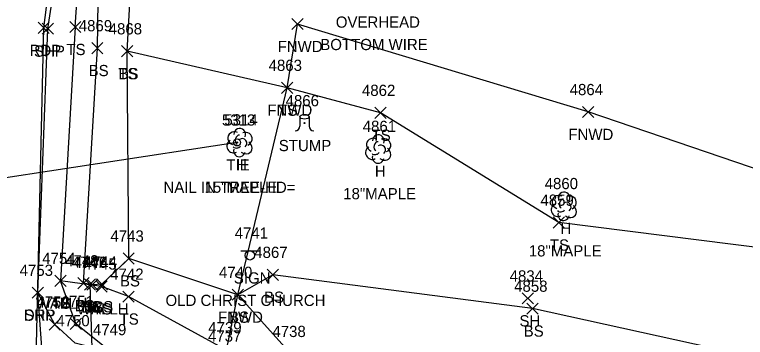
# Model space of a CAD drawing. Extents: x 1601151 to 1602912, y 499508 to 501770.
# Drawn here: x 1601465.7 to 1601596, y 501249.2 to 501306.7 of the extents above; entities that cross this region are included whole.
import ezdxf

# ---------------------------------------------------------------- set-up
doc = ezdxf.new("R2010")
doc.units = 0
for name, color, linetype in [('C_A', 7, 'Continuous'), ('C_C', 7, 'Continuous'), ('C_I', 7, 'Continuous'), ('CBP', 7, 'Continuous'), ('CBT', 7, 'Continuous'), ('D_A', 7, 'Continuous'), ('D_I', 7, 'Continuous'), ('D_TIC', 7, 'Continuous'), ('DCP', 7, 'Continuous'), ('DHW', 7, 'Continuous'), ('L_A', 7, 'Continuous'), ('L_C', 7, 'Continuous'), ('L_I', 7, 'Continuous'), ('L_TIC', 7, 'Continuous'), ('LELB', 7, 'Continuous'), ('LFNC', 7, 'Continuous'), ('LTD', 7, 'Continuous'), ('LTS', 7, 'Continuous'), ('P_A', 7, 'Continuous'), ('P_I', 7, 'Continuous'), ('P_TIC', 7, 'Continuous'), ('PET', 7, 'Continuous'), ('PSP', 7, 'Continuous'), ('R_A', 7, 'Continuous'), ('R_I', 7, 'Continuous'), ('R_TIC', 7, 'Continuous'), ('RDP', 7, 'Continuous'), ('S_A', 7, 'Continuous'), ('S_C', 7, 'Continuous'), ('S_I', 7, 'Continuous'), ('SSGN', 7, 'Continuous'), ('U_A', 7, 'Continuous'), ('U_C', 7, 'Continuous')]:
    doc.layers.add(name, color=color, linetype=linetype)

msp = doc.modelspace()

# ---------------------------------------------------------------- linework, layer by layer
at = {"layer": 'CBP'}
for radius in [0.625, 0.0833]:
    msp.add_circle((1601505.35, 501283.95), radius, dxfattribs=at)
at = {"layer": 'CBT'}
msp.add_lwpolyline([(1601505.35, 501283.95), (1601430.56, 501272.53)], dxfattribs=at)
at = {"layer": 'D_TIC'}
for points in [[(1601472.85, 501258.29), (1601474.85, 501260.29)], [(1601474.85, 501258.29), (1601472.85, 501260.29)], [(1601478.12, 501257.61), (1601480.12, 501259.61)], [(1601480.12, 501257.61), (1601478.12, 501259.61)], [(1601480.19, 501257.28), (1601482.19, 501259.28)], [(1601482.19, 501257.28), (1601480.19, 501259.28)]]:
    msp.add_lwpolyline(points, dxfattribs=at)
at = {"layer": 'DCP'}
msp.add_lwpolyline([(1601480.01, 501230.14), (1601479.12, 501258.61)], dxfattribs=at)
at = {"layer": 'DHW'}
msp.add_lwpolyline([(1601481.19, 501258.28), (1601473.85, 501259.29)], dxfattribs=at)
at = {"layer": 'L_TIC'}
for points in [[(1601475.49, 501303.53), (1601477.49, 501305.53)], [(1601477.49, 501303.53), (1601475.49, 501305.53)], [(1601515.13, 501304.06), (1601517.13, 501306.06)], [(1601517.13, 501304.06), (1601515.13, 501306.06)], [(1601515.13, 501304.06), (1601517.13, 501306.06)], [(1601517.13, 501304.06), (1601515.13, 501306.06)], [(1601479.43, 501299.77), (1601481.43, 501301.77)], [(1601481.43, 501299.77), (1601479.43, 501301.77)], [(1601484.76, 501299.21), (1601486.76, 501301.21)], [(1601486.76, 501299.21), (1601484.76, 501301.21)], [(1601484.76, 501299.21), (1601486.76, 501301.21)], [(1601486.76, 501299.21), (1601484.76, 501301.21)], [(1601513.29, 501292.7), (1601515.29, 501294.7)], [(1601515.29, 501292.7), (1601513.29, 501294.7)], [(1601513.29, 501292.7), (1601515.29, 501294.7)], [(1601515.29, 501292.7), (1601513.29, 501294.7)], [(1601529.94, 501288.24), (1601531.94, 501290.24)], [(1601531.94, 501288.24), (1601529.94, 501290.24)], [(1601567, 501288.38), (1601569, 501290.38)], [(1601569, 501288.38), (1601567, 501290.38)], [(1601561.75, 501268.66), (1601563.75, 501270.66)], [(1601563.75, 501268.66), (1601561.75, 501270.66)], [(1601485.02, 501262.27), (1601487.02, 501264.27)], [(1601487.02, 501262.27), (1601485.02, 501264.27)], [(1601485.02, 501262.27), (1601487.02, 501264.27)], [(1601487.02, 501262.27), (1601485.02, 501264.27)], [(1601510.72, 501259.36), (1601512.72, 501261.36)], [(1601512.72, 501259.36), (1601510.72, 501261.36)], [(1601472.85, 501258.29), (1601474.85, 501260.29)], [(1601474.85, 501258.29), (1601472.85, 501260.29)], [(1601476.94, 501257.85), (1601478.94, 501259.85)], [(1601478.94, 501257.85), (1601476.94, 501259.85)], [(1601478.12, 501257.61), (1601480.12, 501259.61)], [(1601480.12, 501257.61), (1601478.12, 501259.61)], [(1601478.54, 501257.59), (1601480.54, 501259.59)], [(1601480.54, 501257.59), (1601478.54, 501259.59)], [(1601480.25, 501257.66), (1601482.25, 501259.66)], [(1601482.25, 501257.66), (1601480.25, 501259.66)], [(1601480.19, 501257.28), (1601482.19, 501259.28)], [(1601482.19, 501257.28), (1601480.19, 501259.28)], [(1601484.98, 501255.46), (1601486.98, 501257.46)], [(1601486.98, 501255.46), (1601484.98, 501257.46)], [(1601504.47, 501255.8), (1601506.47, 501257.8)], [(1601506.47, 501255.8), (1601504.47, 501257.8)], [(1601504.47, 501255.8), (1601506.47, 501257.8)], [(1601506.47, 501255.8), (1601504.47, 501257.8)], [(1601556.24, 501255.15), (1601558.24, 501257.15)], [(1601558.24, 501255.15), (1601556.24, 501257.15)], [(1601557.05, 501253.32), (1601559.05, 501255.32)], [(1601559.05, 501253.32), (1601557.05, 501255.32)], [(1601475.57, 501250.6), (1601477.57, 501252.6)], [(1601477.57, 501250.6), (1601475.57, 501252.6)]]:
    msp.add_lwpolyline(points, dxfattribs=at)
at = {"layer": 'LELB'}
for points in [[(1601476.49, 501304.53), (1601478.93, 501340.78), (1601483.82, 501372.17), (1601493.27, 501419.11), (1601502.01, 501462.34), (1601513.24, 501514.09), (1601519.29, 501544.8)], [(1601486.02, 501263.27), (1601481.25, 501258.66), (1601479.54, 501258.59), (1601479.12, 501258.61), (1601477.94, 501258.85), (1601480.43, 501300.77), (1601480.94, 501334.18), (1601485.69, 501371.5), (1601485.76, 501372.59), (1601494.84, 501418.67), (1601503.71, 501461.98), (1601514.66, 501513.83), (1601522.81, 501541.12), (1601521.69, 501544.36)], [(1601514.92, 501246.25), (1601505.47, 501256.8), (1601486.02, 501263.27), (1601485.76, 501300.21), (1601487.94, 501339.81), (1601496.98, 501373.17)], [(1601476.49, 501304.53), (1601473.85, 501259.29)], [(1601666.94, 501224.13), (1601649.13, 501230.84), (1601644.06, 501241.55), (1601653.65, 501247.39), (1601634.42, 501254.81), (1601606.58, 501264.14), (1601562.75, 501269.66), (1601530.94, 501289.24), (1601514.29, 501293.7), (1601485.76, 501300.21)], [(1601511.72, 501260.36), (1601505.47, 501256.8)], [(1601664.07, 501218.13), (1601645.33, 501229.07), (1601628.63, 501238.53), (1601602.89, 501244.46), (1601558.05, 501254.32), (1601511.72, 501260.36)], [(1601482.9, 501246.57), (1601476.57, 501251.6), (1601473.85, 501259.29)], [(1601514.92, 501246.25), (1601503.48, 501246.93), (1601485.98, 501256.46), (1601481.19, 501258.28)]]:
    msp.add_lwpolyline(points, dxfattribs=at)
at = {"layer": 'LFNC'}
for points in [[(1601503.43, 501245.43), (1601503.48, 501246.93), (1601505.47, 501256.8), (1601514.29, 501293.7), (1601516.13, 501305.06)], [(1601673.34, 501255.62), (1601634.03, 501267.87), (1601610.24, 501275.02), (1601568, 501289.38), (1601516.13, 501305.06)]]:
    msp.add_lwpolyline(points, dxfattribs=at)
at = {"layer": 'LTD'}
for p, q in [((1601505.77, 501283.98), (1601505.77, 501283.98)), ((1601505.77, 501283.98), (1601505.77, 501283.98)), ((1601530.51, 501282.82), (1601530.51, 501282.82)), ((1601530.51, 501282.82), (1601530.51, 501282.82)), ((1601563.62, 501272.62), (1601563.62, 501272.62)), ((1601563.62, 501272.62), (1601563.62, 501272.62))]:
    msp.add_line(p, q, dxfattribs=at)
for centre in [(1601505.82, 501285.41), (1601530.56, 501284.25), (1601563.67, 501274.05)]:
    msp.add_arc(centre, 1.05, 335.5272, 180.9563, dxfattribs=at)
for centre, major_axis, ratio, start_param, end_param in [((1601504.98, 501284.64), (1.21, -0.51), 0.895232, 1.570796, 4.712389), ((1601506.81, 501284.56), (-1.14, -0.48), 0.949671, 1.570796, 4.712389), ((1601504.69, 501283.27), (0.58, -1.04), 0.959034, 3.141593, 6.283185), ((1601505.56, 501284.44), (-0.208, -0.792), 0.645439, 3.141593, 6.283185), ((1601506.27, 501283.81), (-0.5, 0.667), 0.989748, 3.141593, 6.283185), ((1601529.72, 501283.49), (1.21, -0.51), 0.895232, 1.570796, 4.712389), ((1601530.3, 501283.28), (-0.208, -0.792), 0.645439, 3.141593, 6.283185), ((1601531.55, 501283.4), (-1.14, -0.48), 0.949671, 1.570796, 4.712389), ((1601505.31, 501283.23), (-0.625, -0.083), 0.423636, 0, 3.141593), ((1601506.77, 501283.15), (-1.09, 0.79), 0.841452, 1.570796, 4.712389), ((1601529.43, 501282.11), (0.58, -1.04), 0.959034, 3.141593, 6.283185), ((1601531.01, 501282.65), (-0.5, 0.667), 0.989748, 3.141593, 6.283185), ((1601531.51, 501281.99), (-1.09, 0.79), 0.841452, 1.570796, 4.712389), ((1601505.77, 501282.48), (0.26, 1.06), 0.942809, 1.570796, 4.712389), ((1601530.51, 501281.32), (0.26, 1.06), 0.942809, 1.570796, 4.712389), ((1601530.05, 501282.07), (-0.625, -0.083), 0.423636, 0, 3.141593), ((1601562.83, 501273.28), (1.21, -0.51), 0.895232, 1.570796, 4.712389), ((1601563.41, 501273.07), (-0.208, -0.792), 0.645439, 3.141593, 6.283185), ((1601564.66, 501273.2), (-1.14, -0.48), 0.949671, 1.570796, 4.712389), ((1601562.54, 501271.91), (0.58, -1.04), 0.959034, 3.141593, 6.283185), ((1601564.12, 501272.45), (-0.5, 0.667), 0.989748, 3.141593, 6.283185), ((1601564.62, 501271.78), (-1.09, 0.79), 0.841452, 1.570796, 4.712389), ((1601563.62, 501271.12), (0.26, 1.06), 0.942809, 1.570796, 4.712389), ((1601563.16, 501271.87), (-0.625, -0.083), 0.423636, 0, 3.141593)]:
    msp.add_ellipse(centre, major_axis=major_axis, ratio=ratio, start_param=start_param, end_param=end_param, dxfattribs=at)
at = {"layer": 'LTS'}
for p, q in [((1601516.54, 501288.54), (1601516.54, 501286.87)), ((1601518.21, 501288.37), (1601518.21, 501288.54)), ((1601518.21, 501288.54), (1601518.21, 501286.87)), ((1601517.38, 501287.4), (1601517.38, 501287.4)), ((1601517.38, 501287.4), (1601517.38, 501287.4)), ((1601517.38, 501287.37), (1601517.38, 501287.37))]:
    msp.add_line(p, q, dxfattribs=at)
msp.add_circle((1601517.38, 501287.4), 0.0833, dxfattribs=at)
for centre, start, end in [((1601515.71, 501286.87), 270, 360), ((1601519.04, 501286.87), 180, 270)]:
    msp.add_arc(centre, 0.833, start, end, dxfattribs=at)
msp.add_ellipse((1601517.38, 501288.54), major_axis=(-0.833, 0), ratio=0.5, dxfattribs=at)
at = {"layer": 'P_TIC'}
for points in [[(1601469.85, 501303.37), (1601471.85, 501305.37)], [(1601471.85, 501303.37), (1601469.85, 501305.37)], [(1601470.6, 501303.23), (1601472.6, 501305.23)], [(1601472.6, 501303.23), (1601470.6, 501305.23)], [(1601468.82, 501256.16), (1601470.82, 501258.16)], [(1601470.82, 501256.16), (1601468.82, 501258.16)]]:
    msp.add_lwpolyline(points, dxfattribs=at)
at = {"layer": 'PET'}
msp.add_lwpolyline([(1601544.22, 500876.26), (1601539.18, 500895.59), (1601526.95, 500943.37), (1601516.32, 500985.83), (1601505.44, 501027.92), (1601495.1, 501070.93), (1601487, 501107.14), (1601479.48, 501143.91), (1601474.16, 501178.21), (1601471.72, 501199.66), (1601469.2, 501232.53), (1601470.85, 501304.37), (1601475.76, 501342.26), (1601481.23, 501372.74), (1601489.71, 501419.6), (1601498.83, 501463.24), (1601509.83, 501514.72), (1601518.29, 501552.56), (1601529.19, 501602.72), (1601530.09, 501606.93), (1601533.57, 501622.36), (1601544.66, 501669.88)], dxfattribs=at)
at = {"layer": 'PSP'}
msp.add_lwpolyline([(1601528.9, 500943.6), (1601517.98, 500986.13), (1601507.44, 501028.32), (1601496.62, 501071.21), (1601488.24, 501107.28), (1601480.68, 501144.12), (1601475.12, 501178.17), (1601472.51, 501199.52), (1601470.88, 501228.6), (1601471.76, 501230.34), (1601469.82, 501257.16), (1601471.6, 501304.23), (1601477.35, 501341.75), (1601482.3, 501372.17), (1601491.34, 501419.44), (1601500.56, 501462.85), (1601511.15, 501514.36), (1601520.07, 501552.2), (1601531.25, 501603.07), (1601534.57, 501619.48), (1601535.23, 501620.04), (1601536.15, 501623.42), (1601535.02, 501624.1), (1601546.22, 501669.66)], dxfattribs=at)
at = {"layer": 'R_TIC'}
for points in [[(1601468.82, 501256.16), (1601470.82, 501258.16)], [(1601470.82, 501256.16), (1601468.82, 501258.16)], [(1601471.82, 501250.49), (1601473.82, 501252.49)], [(1601473.82, 501250.49), (1601471.82, 501252.49)]]:
    msp.add_lwpolyline(points, dxfattribs=at)
at = {"layer": 'RDP'}
msp.add_lwpolyline([(1601471.76, 501230.34), (1601477.63, 501235.27), (1601478.91, 501235.6), (1601482.81, 501236.29), (1601495.76, 501233.86), (1601500.21, 501232.72), (1601502.92, 501242.9), (1601482.9, 501246.57), (1601476.45, 501248.17), (1601472.82, 501251.49), (1601469.82, 501257.16)], dxfattribs=at)
at = {"layer": 'SSGN'}
for p, q in [((1601506, 501264.65), (1601509.33, 501264.65)), ((1601507.64, 501263.82), (1601507.64, 501263.82))]:
    msp.add_line(p, q, dxfattribs=at)
msp.add_circle((1601507.64, 501263.82), 0.833, dxfattribs=at)

# ---------------------------------------------------------------- texts
at = {"layer": 'C_A'}
msp.add_text('TIE', height=2, dxfattribs=at).set_placement((1601503.43, 501278.95))
at = {"layer": 'C_C'}
msp.add_text('NAIL IN TREE-HD=', height=2, dxfattribs=at).set_placement((1601492.22, 501274.95))
at = {"layer": 'C_I'}
msp.add_text('5313', height=2, dxfattribs=at).set_placement((1601502.66, 501286.95))
at = {"layer": 'D_A'}
for s, p in [('WALLH', (1601469.44, 501254.29)), ('P', (1601478.5, 501253.61)), ('WALLH', (1601476.78, 501253.28))]:
    msp.add_text(s, height=2, dxfattribs=at).set_placement(p)
at = {"layer": 'D_I'}
for s, p in [('4754', (1601470.59, 501262.29)), ('4747', (1601475.86, 501261.61)), ('4745', (1601477.93, 501261.28))]:
    msp.add_text(s, height=2, dxfattribs=at).set_placement(p)
at = {"layer": 'L_A'}
for s, p in [('TS', (1601474.9, 501299.53)), ('FNWD', (1601512.59, 501300.06)), ('FNWD', (1601512.59, 501300.06)), ('BS', (1601478.87, 501295.77)), ('TS', (1601484.17, 501295.21)), ('BS', (1601484.2, 501295.21)), ('FNWD', (1601510.75, 501288.7)), ('TS', (1601512.7, 501288.7)), ('TS', (1601529.35, 501284.24)), ('FNWD', (1601564.46, 501284.38)), ('STUMP', (1601512.8, 501282.4)), ('H', (1601505.2, 501278.98)), ('H', (1601529.94, 501277.82)), ('H', (1601563.05, 501267.62)), ('TS', (1601561.16, 501264.66)), ('BS', (1601484.46, 501258.27)), ('BS', (1601484.46, 501258.27)), ('BS', (1601510.16, 501255.36)), ('TS', (1601472.26, 501254.29)), ('BS', (1601476.38, 501253.85)), ('BS', (1601477.56, 501253.61)), ('BS', (1601477.98, 501253.59)), ('BS', (1601479.69, 501253.66)), ('TS', (1601479.6, 501253.28)), ('TS', (1601484.39, 501251.46)), ('FNWD', (1601501.94, 501251.8)), ('BS', (1601503.92, 501251.8)), ('SH', (1601555.73, 501251.15)), ('BS', (1601556.49, 501249.32))]:
    msp.add_text(s, height=2, dxfattribs=at).set_placement(p)
at = {"layer": 'L_C'}
for s, p in [('15"MAPLE', (1601499.55, 501274.98)), ('18"MAPLE', (1601524.29, 501273.82)), ('18"MAPLE', (1601557.4, 501263.62))]:
    msp.add_text(s, height=2, dxfattribs=at).set_placement(p)
at = {"layer": 'L_I'}
for s, p in [('4869', (1601477.11, 501303.77)), ('4868', (1601482.45, 501303.21)), ('4868', (1601482.45, 501303.21)), ('4863', (1601510.98, 501296.7)), ('4863', (1601510.98, 501296.7)), ('4862', (1601527.63, 501292.24)), ('4864', (1601564.69, 501292.38)), ('4866', (1601514.01, 501290.4)), ('5314', (1601503.08, 501286.98)), ('4861', (1601527.77, 501285.82)), ('4860', (1601560.23, 501275.62)), ('4859', (1601559.48, 501272.66)), ('4743', (1601482.76, 501266.27)), ('4743', (1601482.76, 501266.27)), ('4867', (1601508.42, 501263.36)), ('4754', (1601470.59, 501262.29)), ('4748', (1601474.68, 501261.85)), ('4747', (1601475.86, 501261.61)), ('4746', (1601476.23, 501261.59)), ('4745', (1601477.93, 501261.28)), ('4744', (1601477.99, 501261.66)), ('4742', (1601482.72, 501259.46)), ('4740', (1601502.13, 501259.8)), ('4740', (1601502.13, 501259.8)), ('4834', (1601553.98, 501259.15)), ('4858', (1601554.79, 501257.32)), ('4751', (1601473.88, 501254.6)), ('4749', (1601479.64, 501249.57)), ('4739', (1601500.21, 501249.93)), ('4739', (1601500.21, 501249.93)), ('4737', (1601500.17, 501248.43)), ('4738', (1601511.66, 501249.25)), ('4738', (1601511.66, 501249.25))]:
    msp.add_text(s, height=2, dxfattribs=at).set_placement(p)
at = {"layer": 'P_A'}
for s, p in [('RDP', (1601468.34, 501299.37)), ('SHP', (1601469.13, 501299.23)), ('SHP', (1601467.36, 501252.16))]:
    msp.add_text(s, height=2, dxfattribs=at).set_placement(p)
at = {"layer": 'P_I'}
msp.add_text('4753', height=2, dxfattribs=at).set_placement((1601466.56, 501260.16))
at = {"layer": 'R_A'}
msp.add_text('DRP', height=2, dxfattribs=at).set_placement((1601467.31, 501252.16))
at = {"layer": 'R_I'}
for s, p in [('4753', (1601466.56, 501260.16)), ('4752', (1601469.56, 501254.49)), ('4750', (1601473.11, 501251.17)), ('4749', (1601479.64, 501249.57))]:
    msp.add_text(s, height=2, dxfattribs=at).set_placement(p)
at = {"layer": 'S_A'}
msp.add_text('SIGN', height=2, dxfattribs=at).set_placement((1601504.78, 501258.79))
at = {"layer": 'S_C'}
msp.add_text('OLD CHRIST CHURCH', height=2, dxfattribs=at).set_placement((1601492.59, 501254.79))
at = {"layer": 'S_I'}
msp.add_text('4741', height=2, dxfattribs=at).set_placement((1601504.93, 501266.79))
at = {"layer": 'U_A'}
msp.add_text('OVERHEAD', height=2, dxfattribs=at).set_placement((1601522.97, 501304.41))
at = {"layer": 'U_C'}
msp.add_text('BOTTOM WIRE', height=2, dxfattribs=at).set_placement((1601520.2, 501300.41))

doc.saveas('drawing.dxf')
